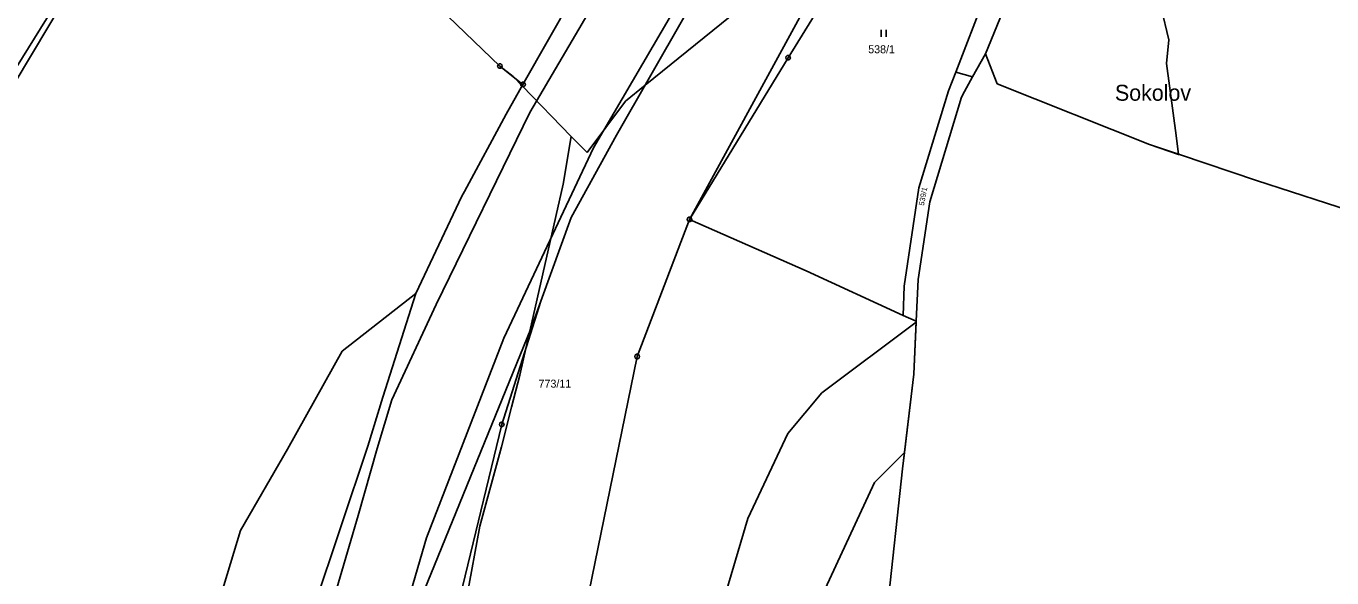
# Model space of a CAD drawing. Extents: x -759699 to -757730, y -1172308 to -1170857.
# Drawn here: x -759560 to -759282.5, y -1171996 to -1171878.7 of the extents above; entities that cross this region are included whole.
import ezdxf

# ---------------------------------------------------------------- set-up
doc = ezdxf.new("R2010")
doc.units = 0
for name, color, linetype in [('Vrstva 1', 7, 'Continuous'), ('Vrstva 11', 7, 'Continuous'), ('Vrstva 12', 7, 'Continuous'), ('Vrstva 2', 7, 'Continuous'), ('Vrstva 3', 7, 'Continuous'), ('Vrstva 4', 7, 'Continuous'), ('Vrstva 7', 7, 'Continuous'), ('Vrstva 8', 7, 'Continuous')]:
    doc.layers.add(name, color=color, linetype=linetype)

msp = doc.modelspace()

# ---------------------------------------------------------------- linework, layer by layer
at = {"layer": 'Vrstva 1'}
for p, q in [((-759398.07, -1171885.47), (-759366.01, -1171833.4)), ((-759530.79, -1171837.99), (-759568.11, -1171900.29)), ((-759362.45, -1171888.53), (-759347.4, -1171849.35)), ((-759342.9, -1171852.37), (-759356.15, -1171884.62)), ((-759438.64, -1171863.35), (-759454.4, -1171891.14)), ((-759459.29, -1171887.24), (-759472.23, -1171874.88)), ((-759420.24, -1171876.89), (-759434.51, -1171901.89)), ((-759395.54, -1171876.83), (-759419.02, -1171919.82)), ((-759356.15, -1171884.62), (-759358.87, -1171889.54)), ((-759353.67, -1171891.01), (-759356.15, -1171884.62)), ((-759454.4, -1171891.14), (-759459.29, -1171887.24)), ((-759419.02, -1171919.82), (-759398.07, -1171885.47)), ((-759363.97, -1171892.5), (-759362.45, -1171888.53)), ((-759358.87, -1171889.54), (-759362.45, -1171888.53)), ((-759358.87, -1171889.54), (-759360.59, -1171892.64)), ((-759454.4, -1171891.14), (-759457.98, -1171897.46)), ((-759370.28, -1171913.11), (-759363.97, -1171892.5)), ((-759360.59, -1171892.64), (-759361.24, -1171893.81)), ((-759321.24, -1171903.89), (-759353.67, -1171891.01)), ((-759361.24, -1171893.81), (-759367.93, -1171916.07)), ((-759457.98, -1171897.46), (-759466.81, -1171913.86)), ((-759434.51, -1171901.89), (-759444.13, -1171919.4)), ((-759314.71, -1171906.13), (-759321.24, -1171903.89)), ((-759298.52, -1171911.55), (-759314.71, -1171906.13)), ((-759275.37, -1171919.1), (-759298.52, -1171911.55)), ((-759477.17, -1171935.58), (-759467.38, -1171914.91)), ((-759466.81, -1171913.86), (-759467.38, -1171914.91)), ((-759373.37, -1171934.01), (-759370.28, -1171913.11)), ((-759367.93, -1171916.07), (-759370.45, -1171932.56)), ((-759450.58, -1171937.17), (-759444.13, -1171919.4)), ((-759430.13, -1171948.96), (-759419.02, -1171919.82)), ((-759419.02, -1171919.82), (-759394.26, -1171930.72)), ((-759394.26, -1171930.72), (-759373.6, -1171940.21)), ((-759373.6, -1171940.21), (-759373.37, -1171934.01)), ((-759370.85, -1171941.47), (-759370.45, -1171932.56)), ((-759492.82, -1171947.84), (-759477.17, -1171935.58)), ((-759484.19, -1171957.57), (-759477.17, -1171935.58)), ((-759450.58, -1171937.17), (-759458.91, -1171963.39)), ((-759451.89, -1171940.77), (-759450.58, -1171937.17)), ((-759373.6, -1171940.21), (-759370.85, -1171941.47)), ((-759452.74, -1171943.04), (-759476.19, -1172000.56)), ((-759451.89, -1171940.77), (-759452.74, -1171943.04)), ((-759370.86, -1171941.64), (-759390.93, -1171956.69)), ((-759370.86, -1171941.64), (-759371.36, -1171952.71)), ((-759370.85, -1171941.47), (-759370.86, -1171941.64)), ((-759504.41, -1171968.66), (-759492.82, -1171947.84)), ((-759430.13, -1171948.96), (-759444.14, -1172017.45)), ((-759373.36, -1171969.34), (-759371.36, -1171952.71)), ((-759390.93, -1171956.69), (-759398.12, -1171965.32)), ((-759487.37, -1171967.99), (-759484.19, -1171957.57)), ((-759470.68, -1172012.13), (-759458.91, -1171963.39)), ((-759506.88, -1172026.13), (-759487.37, -1171967.99)), ((-759398.12, -1171965.32), (-759406.63, -1171983.37)), ((-759514.41, -1171985.91), (-759504.41, -1171968.66)), ((-759379.74, -1171975.75), (-759373.36, -1171969.34)), ((-759373.78, -1171972.82), (-759373.36, -1171969.34)), ((-759373.78, -1171972.82), (-759380.16, -1172031.84)), ((-759393.04, -1172004.47), (-759379.74, -1171975.75)), ((-759406.63, -1171983.37), (-759412.61, -1172003.66)), ((-759537.32, -1172061.35), (-759514.41, -1171985.91))]:
    msp.add_line(p, q, dxfattribs=at)
at = {"layer": 'Vrstva 11'}
for p, q in [((-759569.24, -1171899.05), (-759535.8, -1171845.12)), ((-759428.46, -1171891.29), (-759403.63, -1171871.19)), ((-759472.23, -1171874.88), (-759459.29, -1171887.24)), ((-759318.82, -1171874.85), (-759317.17, -1171881.64)), ((-759317.17, -1171881.64), (-759317.63, -1171886.72)), ((-759356.15, -1171884.62), (-759358.87, -1171889.54)), ((-759353.67, -1171891.01), (-759356.15, -1171884.62)), ((-759459.29, -1171887.24), (-759456.49, -1171889.47)), ((-759317.63, -1171886.72), (-759315.61, -1171901.98)), ((-759456.49, -1171889.47), (-759454.57, -1171891.45)), ((-759358.87, -1171889.54), (-759360.59, -1171892.64)), ((-759454.57, -1171891.45), (-759444.13, -1171902.19)), ((-759432.63, -1171894.67), (-759428.46, -1171891.29)), ((-759360.59, -1171892.64), (-759361.24, -1171893.81)), ((-759321.24, -1171903.89), (-759353.67, -1171891.01)), ((-759440.76, -1171905.61), (-759432.63, -1171894.67)), ((-759361.24, -1171893.81), (-759367.93, -1171916.07)), ((-759444.13, -1171902.19), (-759445.89, -1171912.34)), ((-759444.13, -1171902.19), (-759440.76, -1171905.61)), ((-759315.1, -1171906), (-759321.24, -1171903.89)), ((-759315.61, -1171901.98), (-759315.1, -1171906)), ((-759314.71, -1171906.13), (-759315.1, -1171906)), ((-759298.52, -1171911.55), (-759314.71, -1171906.13)), ((-759445.89, -1171912.34), (-759452.95, -1171943.55)), ((-759275.37, -1171919.1), (-759298.52, -1171911.55)), ((-759367.93, -1171916.07), (-759370.45, -1171932.56)), ((-759370.45, -1171932.56), (-759370.85, -1171941.47)), ((-759370.85, -1171941.47), (-759371.36, -1171952.71)), ((-759452.95, -1171943.55), (-759453.79, -1171947.26)), ((-759453.79, -1171947.26), (-759455.07, -1171952.92)), ((-759455.07, -1171952.92), (-759456.81, -1171959.69)), ((-759371.36, -1171952.71), (-759373.78, -1171972.82)), ((-759456.81, -1171959.69), (-759458.98, -1171968.14)), ((-759458.98, -1171968.14), (-759463.6, -1171985.04)), ((-759373.78, -1171972.82), (-759380.16, -1172031.84)), ((-759463.6, -1171985.04), (-759466.34, -1172000))]:
    msp.add_line(p, q, dxfattribs=at)
at = {"layer": 'Vrstva 12'}
for p, q in [((-759370.86, -1171941.64), (-759390.93, -1171956.69)), ((-759370.86, -1171941.64), (-759371.36, -1171952.71)), ((-759373.36, -1171969.34), (-759371.36, -1171952.71)), ((-759390.93, -1171956.69), (-759398.12, -1171965.32)), ((-759398.12, -1171965.32), (-759406.63, -1171983.37)), ((-759379.74, -1171975.75), (-759373.36, -1171969.34)), ((-759393.04, -1172004.47), (-759379.74, -1171975.75)), ((-759406.63, -1171983.37), (-759412.61, -1172003.66))]:
    msp.add_line(p, q, dxfattribs=at)
at = {"layer": 'Vrstva 3'}
for p, q in [((-759378.26, -1171879.54), (-759378.26, -1171881.04)), ((-759377.26, -1171881.04), (-759377.26, -1171879.54))]:
    msp.add_line(p, q, dxfattribs=at)
at = {"layer": 'Vrstva 4'}
for p, q in [((-759452.92, -1171897.13), (-759428.59, -1171855.62)), ((-759415.44, -1171863.54), (-759439.44, -1171904.64)), ((-759472.87, -1171937.88), (-759452.92, -1171897.13)), ((-759439.44, -1171904.64), (-759458.45, -1171945.06)), ((-759482.29, -1171958.17), (-759472.87, -1171937.88)), ((-759458.45, -1171945.06), (-759474.89, -1171987.52)), ((-759485.35, -1171968.48), (-759482.29, -1171958.17)), ((-759489.42, -1171982.71), (-759485.35, -1171968.48)), ((-759498.9, -1172014.92), (-759489.42, -1171982.71)), ((-759474.89, -1171987.52), (-759484.03, -1172018.64))]:
    msp.add_line(p, q, dxfattribs=at)
at = {"layer": 'Vrstva 8'}
for p, q in [((-759459.41, -1171887.24), (-759459.17, -1171887.24)), ((-759398.19, -1171885.47), (-759397.95, -1171885.47)), ((-759454.52, -1171891.14), (-759454.28, -1171891.14)), ((-759419.14, -1171919.82), (-759418.9, -1171919.82)), ((-759430.25, -1171948.96), (-759430.01, -1171948.96)), ((-759459.03, -1171963.39), (-759458.79, -1171963.39))]:
    msp.add_line(p, q, dxfattribs=at)
for points in [[(-759459.14, -1171886.76), (-759458.89, -1171886.94), (-759458.79, -1171887.23), (-759458.89, -1171887.52), (-759459.14, -1171887.7), (-759459.45, -1171887.7), (-759459.7, -1171887.52), (-759459.8, -1171887.23), (-759459.7, -1171886.94), (-759459.45, -1171886.76)], [(-759397.92, -1171884.99), (-759397.67, -1171885.17), (-759397.57, -1171885.46), (-759397.67, -1171885.75), (-759397.92, -1171885.93), (-759398.23, -1171885.93), (-759398.48, -1171885.75), (-759398.58, -1171885.46), (-759398.48, -1171885.17), (-759398.23, -1171884.99)], [(-759454.25, -1171890.66), (-759454, -1171890.84), (-759453.9, -1171891.13), (-759454, -1171891.42), (-759454.25, -1171891.6), (-759454.56, -1171891.6), (-759454.81, -1171891.42), (-759454.91, -1171891.13), (-759454.81, -1171890.84), (-759454.56, -1171890.66)], [(-759418.87, -1171919.34), (-759418.62, -1171919.52), (-759418.52, -1171919.81), (-759418.62, -1171920.1), (-759418.87, -1171920.28), (-759419.18, -1171920.28), (-759419.43, -1171920.1), (-759419.53, -1171919.81), (-759419.43, -1171919.52), (-759419.18, -1171919.34)], [(-759429.98, -1171948.48), (-759429.73, -1171948.66), (-759429.63, -1171948.95), (-759429.73, -1171949.24), (-759429.98, -1171949.42), (-759430.29, -1171949.42), (-759430.54, -1171949.24), (-759430.64, -1171948.95), (-759430.54, -1171948.66), (-759430.29, -1171948.48)], [(-759458.76, -1171962.91), (-759458.51, -1171963.09), (-759458.41, -1171963.38), (-759458.51, -1171963.67), (-759458.76, -1171963.85), (-759459.07, -1171963.85), (-759459.32, -1171963.67), (-759459.42, -1171963.38), (-759459.32, -1171963.09), (-759459.07, -1171962.91)]]:
    msp.add_lwpolyline(points, close=True, dxfattribs=at)

# ---------------------------------------------------------------- texts
at = {"layer": 'Vrstva 2'}
for s, p in [('538/1', (-759381.046, -1171884.51)), ('773/11', (-759451.093, -1171955.57))]:
    msp.add_text(s, height=1.7, dxfattribs=at).set_placement(p)
msp.add_text('539/1', height=1.14, rotation=79.12547, dxfattribs=at).set_placement((-759369.207, -1171916.95))
at = {"layer": 'Vrstva 7'}
msp.add_text('Sokolov', height=3.4, dxfattribs=at).set_placement((-759328.614, -1171894.6))

doc.saveas('drawing.dxf')
